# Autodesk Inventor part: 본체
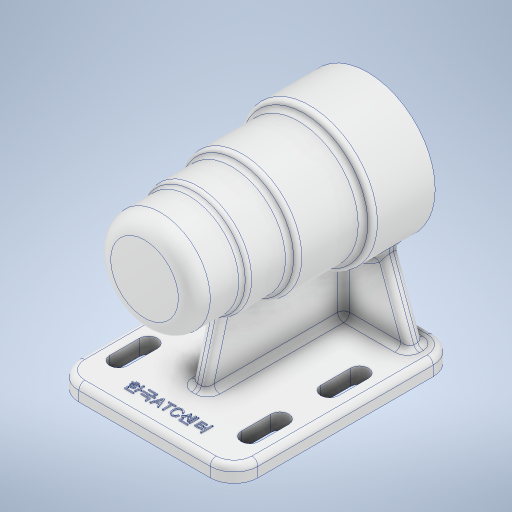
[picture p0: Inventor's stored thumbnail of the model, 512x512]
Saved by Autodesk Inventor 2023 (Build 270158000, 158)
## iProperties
Created: 2022-07
Part Number: 본체
Material: 알루미늄 6061
Document SubType Name: Modeling
Designer: owner
Density: 2.7 g/cm^3
Appearance: 알루미늄 - 평지
Mass: 689.37 g
Surface Area: 704.003 cm^2
Volume: 255.322 cm^3
Author: owner
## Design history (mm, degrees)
sketch "스케치1"
  geometry: L1 (33, 56)-(-33, 56); L2 (-45, 44)-(-45, -44); L3 (-33, -56)-(33, -56); L4 (45, -44)-(45, 44); L5 (45, 56)-(-45, -56); L6 (-45, 56)-(45, -56); A1 r 12 centre (33, 44) between (45, 44) and (33, 56); A2 r 12 centre (33, -44) between (33, -56) and (45, -44); A3 r 12 centre (-33, 44) between (-33, 56) and (-45, 44); A4 r 12 centre (-33, -44) between (-45, -44) and (-33, -56); 1 further point
  constraints: 12 end point, 8 point on circle, 8 point on line, 8 tangent, 4 centre point, 3 equal radius, 2 midpoint, 2 parallel, 1 horizontal, 1 perpendicular
  dimensions: "d0" = 90 distance of L6.end L5.end; "d1" = 112 distance of L5.end L6.start; "d2" = 12 radius of A1
extrude "돌출1" new body sketch "스케치1" distance "d3" = 8; taper "d4" = 0 deg
sketch "스케치2"
  geometry: L1 (-33, -36)-(-33, -21); L2 (-28.5, -36)-(-28.5, -21); L3 (-37.5, -21)-(-37.5, -36); L4 (-33, -56)-(33, -56) reference; L5 (-33, 4)-(-33, 19); L6 (-28.5, 4)-(-28.5, 19); L7 (-37.5, 19)-(-37.5, 4); A1 r 4.5 centre (-33, -36) between (-37.5, -36) and (-28.5, -36); A2 r 4.5 centre (-33, -21) between (-28.5, -21) and (-37.5, -21); A3 r 4.5 centre (-33, 4) between (-37.5, 4) and (-28.5, 4); A4 r 4.5 centre (-33, 19) between (-28.5, 19) and (-37.5, 19); 3 further points
  constraints: 16 end point, 8 point on circle, 8 tangent, 4 centre point, 2 midpoint, 2 parallel, 2 vertical
  dimensions: "d5" = 20 distance from line of L4 L1.start; "d6" = 15 distance of L1.start L1.end; "d7" = 9 distance between parallel lines of L2 L3; "d8" = 33 distance from line of point (0, 0) L1; "d9" = 9 distance between parallel lines of L6 L7; "d10" = 15 distance of L5.start L5.end; "d11" = 25 distance of L5.start L1.end; "d12" = 33 distance from line of point (0, 0) L5
extrude "돌출2" cut sketch "스케치2" distance "d13" = 8; taper "d14" = 0 deg
sketch "스케치4"
  geometry: L1 (0, 0)-(147.887, 0); L2 (70, 56)-(70, -56); L3 (0, -56)-(8, -56) reference; L4 (91, -56)-(91, -41); L5 (91, -41)-(94, -41); L6 (94, -41)-(94, 13); L7 (94, 13)-(91, 13); L8 (91, 13)-(91, 25); L9 (91, 25)-(87.5, 25); L10 (87.5, 25)-(87.5, 43); L11 (87.5, 43)-(86, 43); L12 (86, 43)-(86, 47); L13 (86, 47)-(80.5, 47); L14 (80.5, 47)-(80.5, 50); L15 (80.5, 50)-(70, 50); L16 (70, 50)-(70, 56); L17 (70, 56)-(95, 56); L18 (95, 56)-(95, 32); L19 (95, 32)-(97, 32); L20 (97, 32)-(97, 10); L21 (97, 10)-(100, 10); L22 (100, 10)-(100, -24); L23 (100, -24)-(104, -24); L24 (104, -24)-(104, -56); L25 (104, -56)-(91, -56); 1 further point
  constraints: 48 end point, 17 perpendicular, 3 horizontal, 3 point on line, 2 horizontal alignment, 2 vertical, 1 collinear, 1 midpoint
  dimensions: "d40" = 70 distance from line of L1.start L2; "d41" = 147.88724 distance of L1.start L1.end; "d42" = 112 distance of L2.start L2.end; "d43" = 15 distance of L4.start L4.end; "d44" = 42 diameter of L4 L2; "d45" = 48 diameter of L6 L2; "d46" = 54 distance between parallel lines of L5 L7; "d47" = 12 distance between parallel lines of L9 L7; "d48" = 35 diameter of L10 L2; "d49" = 32 diameter of L12 L2; "d50" = 21 diameter of L14 L2; "d51" = 18 distance between parallel lines of L11 L9; "d52" = 4 distance between parallel lines of L13 L11; "d53" = 3 distance between parallel lines of L13 L15; "d54" = 68 diameter of L24 L2; "d55" = 80 distance between parallel lines of L17 L23; "d56" = 60 diameter of L22 L2; "d57" = 54 diameter of L20 L2; "d58" = 50 diameter of L18 L2; "d59" = 46 distance between parallel lines of L17 L21; "d60" = 24 distance between parallel lines of L17 L19
revolve "회전1" sketch "스케치4" stored, may be unused: angle "d61" = 90 deg
fillet "모깎기1" dims "d62" = 8
node "작업 평면1"
sketch "스케치8"
  geometry: L1 (-4, 8)-(9.591, 45.342); L2 (-4.5, 8)-(4.5, 8) reference; L3 (0, 8)-(-12, 8) reference; L4 (33, 0)-(33, 70); L5 (70, 8)-(56.409, 45.342); L6 (70.5, 8)-(70.5, 0) reference; L7 (-4.5, 8)-(70.5, 8); C1 r 10.5 at (33, 70) reference; 4 further points
  constraints: 8 end point, 2 symmetric about line, 1 point on line, 2 other
  dimensions: "d71" = 8 distance of L3.end L1.start; "d72" = 110 deg angle of L3 L1
extrude "돌출3" join sketch "스케치8" distance "d73" = 8; taper "d74" = 0 deg
sketch "스케치14" dims "d91" = 52
  geometry: C1 r 24 at (0, 0) reference; 3 further points
  constraints: 2 horizontal alignment, 1 coincident, 2 other
hole "구멍1" sketch "스케치14" at (-26, 0) diameter "d84" = 3.242; stored, may be unused: countersink angle "d88" = 90 deg, drill point angle "d90" = 118 deg; dims "d85" = 8, "d86" = 4, "d87" = 2, "d89" = 11
fillet "모깎기2" dims "d95" = 3
chamfer "모따기1" distance "d96" = 1; stored, may be unused: second distance "d97" = 2, angle "d98" = 45 deg
sketch "스케치17"
  geometry: 1 further point
sketch "스케치18"
  geometry: 1 further point
sketch "스케치19"
  geometry: L1 (-33, -56)-(33, -56) reference; 2 further points
  constraints: 1 vertical alignment, 1 other
  dimensions: "d104" = 12 distance from line of L1 point (0, -44)
feature "엠보싱1" sketch "스케치19" dims "d105" = 0.5, "d106" = 0
sketch "스케치26"
  geometry: L1 (8, 29)-(45.342, 18.994); L2 (8, -48)-(45.342, -48) reference; L3 (8, 21)-(8, 36) reference; L4 (45.342, 18.994)-(45.342, -48); L5 (45.342, -40)-(8, -40) reference; L6 (0, -56)-(0, -44) reference; L7 (0, -48)-(45.342, -48); 1 further point
  constraints: 6 end point, 2 perpendicular, 2 point on line
  dimensions: "d127" = 77 distance from line of L2 L1.start; "d128" = 105 deg angle of L3 L1
feature "리브2" sketch "스케치26" dims "d129" = 1, "d130" = 8, "d131" = 0, "d132" = 0, "d133" = 1, "d134" = 1
fillet "모깎기3" dims "d135" = 3
fillet "모깎기4" dims "d136" = 3
node "솔리드1"
mirror "미러1"
pattern_circular "원형 패턴1" dims angle "d93" = 360 deg
feature "A9D066F2-1C7D-4E18-AEED-F7BC21143FA4" dims "d84" = 3.242, "d85" = 8, "d86" = 4, "d87" = 2, "d88" = 90 deg, "d89" = 11, "d90" = 118 deg
other parameters: "d70" = -8
